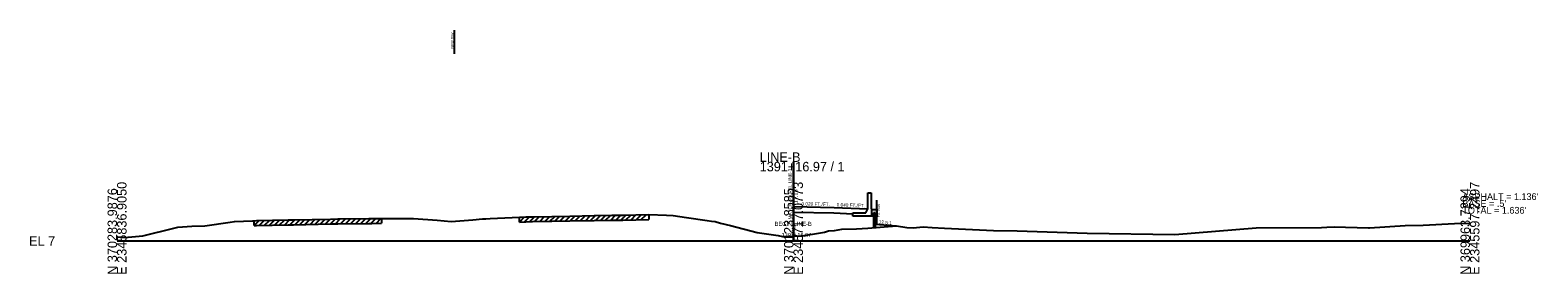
# Model space of a CAD drawing. Extents: x -26 to 2400, y -10 to 9525.
# Drawn here: x -25.7 to 420.1, y -9.7 to 62.3 of the extents above; entities that cross this region are included whole.
import ezdxf

# ---------------------------------------------------------------- set-up
doc = ezdxf.new("R2010")
doc.units = 0
for name, color, linetype in [('RD_GPK_XS_Cell', 7, 'Continuous'), ('RD_XS_Base', 7, 'Continuous'), ('RD_XS_ExGround', 7, 'Continuous'), ('RD_XS_ExPaveRet', 7, 'Continuous'), ('RD_XS_ExRW', 7, 'Continuous'), ('RD_XS_MatchLine', 7, 'Continuous'), ('RD_XS_MedBWall', 7, 'Continuous'), ('RD_XS_NewRW', 7, 'Continuous'), ('RD_XS_Pave', 7, 'Continuous'), ('RD_XS_PaveShd', 7, 'Continuous'), ('RD_XS_TieSlope', 7, 'Continuous'), ('RD_XS_TX_Elev_EX', 7, 'Continuous'), ('RD_XS_TX_Slope', 7, 'Continuous'), ('RD_XS_TX_Station', 7, 'Continuous')]:
    doc.layers.add(name, color=color, linetype=linetype)

msp = doc.modelspace()

# ---------------------------------------------------------------- linework, layer by layer
at = {"layer": 'RD_GPK_XS_Cell'}
for p, q in [((200, 0), (200, 23.37)), ((0, 0), (200, 0)), ((200, 0), (400, 0))]:
    msp.add_line(p, q, dxfattribs=at)
at = {"layer": 'RD_XS_Base'}
for p, q in [((200, 8.52), (211.95, 8.28)), ((211.95, 8.28), (217.58, 8.06))]:
    msp.add_line(p, q, dxfattribs=at)
at = {"layer": 'RD_XS_ExGround'}
msp.add_lwpolyline([(0, 1.2), (0.17, 1.22), (2.48, 1.01), (3.26, 1.15), (7.6, 1.48), (10.77, 2.33), (13.6, 3.03), (17.95, 4.11), (22.12, 4.38), (25.91, 4.5), (33.49, 5.57), (34.75, 5.75), (40.02, 5.98), (40.56, 6), (41.25, 6.02), (50.55, 6.23), (52.12, 6.25), (63.11, 6.46), (65.3, 6.5), (74.45, 6.61), (75.36, 6.62), (78.16, 6.66), (81.97, 6.67), (87.61, 6.69), (94.67, 6.11), (98.79, 5.79), (105.2, 6.29), (108.09, 6.51), (109.07, 6.55), (110.31, 6.61), (118.96, 7.04), (120.84, 7.11), (122.84, 7.17), (128.54, 7.27), (133.85, 7.36), (141.11, 7.49), (146.31, 7.58), (149.54, 7.62), (157.18, 7.79), (162.45, 7.59), (164.43, 7.5), (168.37, 6.94), (174.45, 6.09), (175.8, 5.88), (176.8, 5.73), (178.39, 5.27), (181.4, 4.6), (189.27, 2.5), (195.46, 1.61), (196.75, 1.34), (197.42, 1.3), (199.58, 1.4), (200, 1.41), (202.37, 1.49), (205.57, 1.99), (209.12, 2.65), (210.34, 3), (212.16, 3.11), (214.27, 3.53), (218.64, 3.63), (220.33, 3.72), (222.02, 3.81), (230.48, 4.49), (233.51, 4), (235.37, 3.85), (238.32, 4.2), (240.98, 3.96), (244.6, 3.75), (259.11, 3.08), (266.15, 2.97), (286.79, 2.34), (312.71, 1.88), (336.78, 3.92), (356.12, 3.96), (357.67, 4.11), (359.89, 4.14), (369.96, 3.85), (370.31, 3.86), (380.86, 4.55), (386.2, 4.65), (395.42, 5.21), (400, 5.24)], dxfattribs=at)
at = {"layer": 'RD_XS_ExPaveRet'}
for p, q in [((40.56, 4.57), (42.03, 6.04)), ((40.56, 4.57), (40.56, 6)), ((40.56, 4.57), (41.25, 4.58)), ((41.25, 4.58), (50.55, 4.79)), ((42.06, 4.6), (43.53, 6.07)), ((43.56, 4.63), (45.03, 6.1)), ((45.06, 4.67), (46.53, 6.14)), ((46.56, 4.7), (48.03, 6.17)), ((48.06, 4.73), (49.53, 6.2)), ((49.56, 4.77), (51.02, 6.23)), ((50.55, 4.79), (52.12, 4.82)), ((51.06, 4.8), (52.52, 6.26)), ((52.12, 4.82), (63.11, 5.03)), ((52.56, 4.82), (54.02, 6.29)), ((54.06, 4.85), (55.52, 6.32)), ((55.56, 4.88), (57.02, 6.35)), ((57.06, 4.91), (58.52, 6.38)), ((58.56, 4.94), (60.02, 6.4)), ((60.06, 4.97), (61.52, 6.43)), ((61.56, 5), (63.02, 6.46)), ((63.06, 5.02), (64.52, 6.48)), ((63.11, 5.03), (65.3, 5.06)), ((64.56, 5.05), (66.01, 6.5)), ((65.3, 5.06), (74.45, 5.17)), ((66.06, 5.07), (67.51, 6.52)), ((67.56, 5.09), (69.01, 6.54)), ((69.06, 5.11), (70.51, 6.56)), ((70.56, 5.12), (72.01, 6.58)), ((72.06, 5.14), (73.51, 6.6)), ((73.56, 5.16), (75.01, 6.62)), ((74.45, 5.17), (75.36, 5.19)), ((75.06, 5.18), (76.51, 6.64)), ((75.36, 5.19), (78.16, 5.22)), ((76.56, 5.2), (78.01, 6.66)), ((78.16, 6.66), (78.16, 5.22)), ((118.96, 5.6), (120.44, 7.09)), ((118.96, 5.6), (118.96, 7.04)), ((118.96, 5.6), (120.84, 5.67)), ((120.46, 5.66), (121.94, 7.14)), ((120.84, 5.67), (122.84, 5.73)), ((121.96, 5.7), (123.43, 7.18)), ((122.84, 5.73), (128.54, 5.83)), ((123.46, 5.74), (124.92, 7.2)), ((124.96, 5.77), (126.42, 7.23)), ((126.46, 5.79), (127.92, 7.26)), ((127.96, 5.82), (129.42, 7.28)), ((128.54, 5.83), (133.85, 5.92)), ((129.46, 5.85), (130.92, 7.31)), ((130.96, 5.87), (132.42, 7.34)), ((132.46, 5.9), (133.92, 7.36)), ((133.85, 5.92), (141.11, 6.05)), ((133.96, 5.93), (135.42, 7.39)), ((135.46, 5.95), (136.92, 7.41)), ((136.96, 5.98), (138.42, 7.44)), ((138.46, 6), (139.92, 7.46)), ((139.96, 6.03), (141.42, 7.49)), ((141.11, 6.05), (146.31, 6.14)), ((141.46, 6.05), (142.92, 7.52)), ((142.96, 6.08), (144.42, 7.55)), ((144.46, 6.11), (145.92, 7.57)), ((145.96, 6.14), (147.41, 7.59)), ((146.31, 6.14), (149.54, 6.19)), ((147.46, 6.16), (148.91, 7.61)), ((148.96, 6.18), (150.42, 7.64)), ((149.54, 6.19), (157.18, 6.35)), ((150.46, 6.21), (151.92, 7.67)), ((151.96, 6.24), (153.42, 7.71)), ((153.46, 6.27), (154.92, 7.74)), ((154.96, 6.3), (156.42, 7.77)), ((157.18, 7.79), (157.18, 6.35))]:
    msp.add_line(p, q, dxfattribs=at)
at = {"layer": 'RD_XS_ExRW'}
msp.add_line((224.62, 5.02), (224.62, 12.02), dxfattribs=at)
at = {"layer": 'RD_XS_MatchLine'}
for p, q in [((200, 23.37), (200, 10.16)), ((200, 10.16), (200, 1.41))]:
    msp.add_line(p, q, dxfattribs=at)
at = {"layer": 'RD_XS_MedBWall'}
for p, q in [((222, 9.52), (222, 14.19)), ((222, 14.19), (223, 14.19)), ((222, 9.52), (222, 14.19)), ((222, 14.19), (223, 14.19)), ((223, 14.19), (223, 9.52)), ((221.37, 8.35), (221.86, 9.35)), ((221.86, 9.35), (222, 9.52)), ((223, 9.52), (223.08, 9.52)), ((223.08, 9.52), (223.08, 7.35)), ((223.08, 9.35), (223.15, 9.35)), ((223.15, 9.35), (224.65, 9.35)), ((223.15, 7.35), (223.15, 9.35)), ((224.65, 9.35), (224.65, 7.35)), ((217.58, 7.35), (217.58, 8.35)), ((217.58, 8.35), (221.37, 8.35)), ((223.08, 7.35), (217.58, 7.35)), ((223.65, 7.35), (223.15, 7.35)), ((224.15, 8.35), (223.65, 8.35)), ((223.65, 8.35), (223.65, 7.35)), ((223.65, 7.35), (223.65, 3.94)), ((224.15, 7.35), (224.15, 8.35)), ((224.65, 7.35), (224.15, 7.35)), ((224.15, 7.35), (224.15, 3.98))]:
    msp.add_line(p, q, dxfattribs=at)
at = {"layer": 'RD_XS_NewRW'}
msp.add_line((99.73, 55.26), (99.73, 62.26), dxfattribs=at)
at = {"layer": 'RD_XS_Pave'}
msp.add_line((200, 10.16), (212, 9.92), dxfattribs=at)
at = {"layer": 'RD_XS_PaveShd'}
msp.add_line((212, 9.92), (222, 9.52), dxfattribs=at)
at = {"layer": 'RD_XS_TieSlope'}
msp.add_line((224.15, 4.99), (230.48, 4.49), dxfattribs=at)

# ---------------------------------------------------------------- texts
at = {"layer": 'RD_GPK_XS_Cell'}
for s, p in [('1391+16.97 / 1', (190, 20.57)), ('LINE-B', (190, 23.37)), ('EL 7', (-26, -1.4))]:
    msp.add_text(s, height=2.8, dxfattribs=at).set_placement(p)
for s, p in [('N 370283.9876', (0, -10)), ('E 2345836.9050', (2.8, -10)), ('N 370123.8585', (200, -10)), ('E 2345717.0773', (202.8, -10)), ('N 369963.7294', (400, -10)), ('E 2345597.2497', (402.8, -10))]:
    msp.add_text(s, height=2.8, rotation=90, dxfattribs=at).set_placement(p)
at = {"layer": 'RD_XS_ExRW'}
msp.add_text('EX. R/W ', height=0.75, rotation=90, dxfattribs=at).set_placement((225.61, 7))
at = {"layer": 'RD_XS_MatchLine'}
msp.add_text('MATCH TO REL LINE-3', height=1, rotation=90, dxfattribs=at).set_placement((199.48, 6.39))
at = {"layer": 'RD_XS_NewRW'}
msp.add_text('NEW R/W ', height=0.75, rotation=90, dxfattribs=at).set_placement((99.48, 56.85))
at = {"layer": 'RD_XS_TieSlope'}
for s, p in [("ASPHALT = 1.136'", (397.76, 12.1)), ("TOTAL = 1.636'", (397.76, 8.07)), ("BASE = .5'", (397.76, 10.08))]:
    msp.add_text(s, height=2, dxfattribs=at).set_placement(p)
at = {"layer": 'RD_XS_TX_Elev_EX'}
msp.add_text('8.41', height=1, rotation=90, dxfattribs=at).set_placement((200.5, 1.41))
at = {"layer": 'RD_XS_TX_Slope'}
for s, rotation, p in [('0.020 FT./FT.', 358.8542, (202.36, 10.51)), ('0.040 FT./FT.', 357.7094, (212.75, 10.26)), ('12.5:1', 353.9837, (225.16, 5.17))]:
    msp.add_text(s, height=1, rotation=rotation, dxfattribs=at).set_placement(p)
at = {"layer": 'RD_XS_TX_Station'}
msp.add_text('17.16', height=1.2, rotation=90, dxfattribs=at).set_placement((201.22, 11.11))
for s, p in [('BEGIN LINE-B', (194.44, 4.46)), ('1391+16.97', (196.48, 1.16))]:
    msp.add_text(s, height=1.2, dxfattribs=at).set_placement(p)

doc.saveas('drawing.dxf')
